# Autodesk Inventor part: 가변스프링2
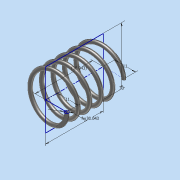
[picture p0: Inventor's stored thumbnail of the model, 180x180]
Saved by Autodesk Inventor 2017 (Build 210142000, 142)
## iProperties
Part Number: 가변스프링2
Material: 강철, 연강
Document SubType Name: Modeling
Designer: MRC
Density: 7.85 g/cm^3
Appearance: 반연마
Mass: 8.40433 g
Surface Area: 21.6868 cm^2
Volume: 1.07061 cm^3
Author: MRC
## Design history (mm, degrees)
sketch "스케치1"
  geometry: L1 (0, 0)-(0, 30.043); L2 (0, 30.043)-(11, 30.043); L3 (0, 0)-(11, 0); C1 r 1 at (11, 0)
  constraints: 6 end point, 1 centre point, 1 coincident, 1 horizontal, 1 parallel, 1 vertical
  dimensions: "d0" = 30.04259 distance of L1.start L1.end (derived); "d1" = 11 distance of L1.end L2.end; "d2" = 11 distance of L1.start L3.end; "d3" = 2 diameter of C1
feature "코일1" sketch "스케치1" pitch "d4" = 10; turns "d6" = 5; dims "d5" = 30.04259 (= d0), "d7" = 0, angle "d8" = 90 deg, angle "d9" = 90 deg, "d10" = 0, "d11" = 0
sketch "스케치2"
  geometry: L1 (30.043, 15)-(0, 15); L2 (0, 15)-(0, -15); L3 (0, -15)-(30.043, -15); L4 (30.043, -15)-(30.043, 15); 2 further points
  constraints: 8 end point, 2 parallel, 1 coincident, 1 horizontal, 1 midpoint, 1 perpendicular
  dimensions: "d12" = 30.04259 distance of L2.end L3.end (= d0); "d13" = 30 distance of L3.end L1.start
extrude "돌출1" sketch "스케치2" stored distance "d14" = 0; taper "d15" = 0 deg
node "솔리드1"
